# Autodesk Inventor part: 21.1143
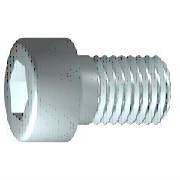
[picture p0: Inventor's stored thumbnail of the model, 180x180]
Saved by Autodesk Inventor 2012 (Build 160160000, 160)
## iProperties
Created: 2006-02
Part Number: 21.1143
Material: Steel, Mild
Description: M6X12 SHCS
Document SubType Name: Modeling
Standard: DIN 7984
Designer: Andy Moles
Standards Organization: DIN
Language: en-US
Size Designation: M6 x 12
Categories: <MemberInstance><Categories><Category DisplayName="Fasteners" InternalName="e4da775c-781d-43d5-af7c-5136215cf5a6" Mnemonic="FSTN"><Category DisplayName="Bolts"
Density: 7.86 g/cm^3
Mass: 4.70792 g
Surface Area: 5.38764 cm^2
Volume: 0.598972 cm^3
Vendor: S
Author: Andy Moles
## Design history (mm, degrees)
body "Solid1"
revolve "Body" stored, may be unused: angle "d10" = 90 deg
sketch "Sketch2"
  geometry: L1 (0, -7)-(0, 7) reference; L2 (-7, 0)-(7, 0) reference; L3 (2.309, 0)-(1.155, -2); L4 (1.155, -2)-(-1.155, -2); L5 (-1.155, -2)-(-2.309, 0); L6 (-2.309, 0)-(-1.155, 2); L7 (-1.155, 2)-(1.155, 2); L8 (1.155, 2)-(2.309, 0); 2 further points
  constraints: 12 end point, 1 coincident, 1 horizontal alignment, 1 point on line, 12 other
extrude "Slot" join sketch "Sketch2" stored distance "d11" = 10; taper "d12" = 0 deg
workplane "Work Plane1"
fillet "Fillet1" dims "d17" = 0.6 (= RR)
feature "Thread" dims "d13" = 12 (= GEL), "d14" = 0
chamfer "Chamfer1" distance "d15" = 0.61345 (= -0.5 x SPD + 0.5 x GD); stored, may be unused: second distance "d16" = 0.61345 (= GUL), angle "d27" = 45 deg
sketch "Sketch1"
  geometry: L1 (0.333, 0)-(12, 0); L2 (12, 0)-(12, 3); L3 (12, 3)-(0, 3); L4 (0, 3)-(0, 3); L5 (0, 3)-(0, 3); L6 (0, 3)-(0, 5); L7 (0, 5)-(-4, 5); L8 (-4, 5)-(-4, 2.309); L9 (-4, 2.309)-(-1, 2.309); L10 (-1, 2.309)-(0.333, 0); L11 (-7.2, 0)-(15.2, 0) reference; L12 (0, -1)-(0, 6) reference; L13 (0, 3)-(0, 3)
  constraints: 22 end point, 6 parallel, 2 collinear, 2 perpendicular, 1 horizontal, 1 point on line
  dimensions: "d1" = 12 distance from line of L3.end L2 (= GEL); "d2" = 0 distance of L4.end L3.end (computed from GAL); "d3" = 4 distance between parallel lines of L8 L6 (= KOH); "d4" = 3 distance of L8.end L9.end (= INTI); "d5" = 60 deg angle of L10 L1; "d6" = 6 diameter of L3 L1 (= GD); "d7" = 6 diameter of L5 L1 (= BDM); "d8" = 4.6188 diameter of L9 L1 (= 1.1547 x SW); "d9" = 10 diameter of L7 L1 (= KOD); "d26" = 12 distance between parallel lines of L12 L2 (= NLG)
other parameters: "GD" = 6 (= NND) [user parameter; used in 2 equation terms], "NLG" = 12 [user parameter; used in 1 equation term], "GEL" = 12 [user parameter; used in 2 equation terms], "KOD" = 10 [user parameter; used in 1 equation term], "KOH" = 4 [user parameter; used in 1 equation term], "INTI" = 3 [user parameter; used in 1 equation term], "GAL" = 0 [user parameter; used in 1 equation term], "GUL" = 0.61345 (= 0.61345 x PTC) [user parameter; used in 1 equation term], "BDM" = 6 (= NND) [user parameter; used in 1 equation term], "SW" = 4 [user parameter; used in 2 equation terms], "RR" = 0.6 [user parameter; used in 1 equation term], "SPD" = 4.7731 (= NND - 1.2269 x PTC) [user parameter; used in 1 equation term], "d19" = 0, "d28" = 0, "d29" = 0, "TOA" = 30 deg [user parameter], "GD1" = 4.7731 (= THREADDIA - 1.2269 x PTC) [user parameter], "THREADDIA" = 6 [user parameter; used in 1 equation term], "FAWI" = 45 deg [user parameter], "ANG" = 120 deg [user parameter], "PTC" = 1 [user parameter; used in 4 equation terms], "NND" = 6 [user parameter; used in 3 equation terms], "E0" = 4.62 (= 1.155 x SW) [user parameter]
